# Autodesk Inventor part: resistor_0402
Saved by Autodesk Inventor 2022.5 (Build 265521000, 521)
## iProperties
Created: 2024-12
Part Number: resistor_0402
Material: Generic
Document SubType Name: Modeling
Designer: AdminForWorker
Density: 1 g/cm^3
Appearance: Default
Title: resistor_0402 v1
Author: AdminForWorker
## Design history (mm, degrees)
feature "Body6"
feature "Body8"
feature "Body19"
body "Solid1"
body "Solid2"
body "Solid3"
